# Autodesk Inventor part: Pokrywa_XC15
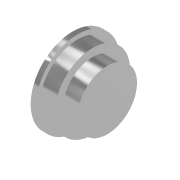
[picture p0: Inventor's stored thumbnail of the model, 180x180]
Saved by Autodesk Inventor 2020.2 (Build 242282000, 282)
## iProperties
Created: 2000-05
Part Number: Pokrywa_XC15
Document SubType Name: Modeling
Designer: F.Stasiak
Stock Number: Pokrywa_XC15
Density: 1 g/cm^3
Material: Default
Appearance: Czarny chrom
Manager: www.cadconsulting.pl
Company: Fabian Stasiak CAD Consulting
Control State: 0
Master: False
Checked Out: False
Shininess: 0.0
Density: 0.0
Volumn: 0.0
Area: 0.0
PropertySet Name: Model Information
Author: F.Stasiak
Subject: Zbiór ćwiczeń. Autodesk Inventor 2020. Kurs podstawowy
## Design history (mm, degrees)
node "Base1"
node "Bryła1"
node "Korpusy bryłowe"
node "Korpusy powierzchniowe"
